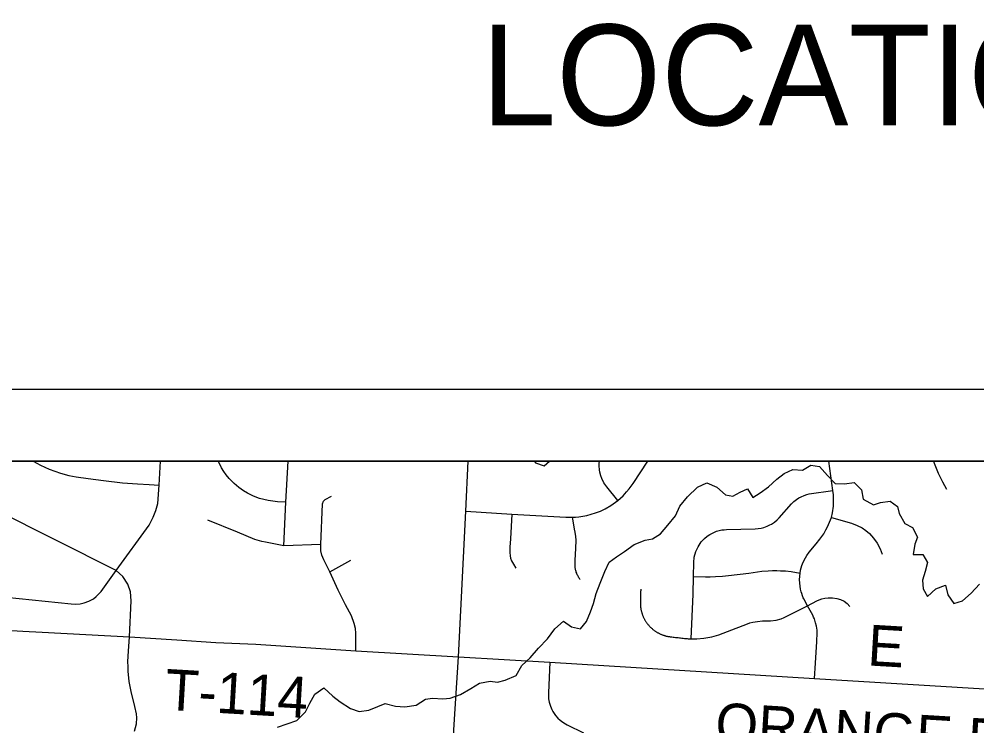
# Model space of a CAD drawing. Extents: x 0 to 34, y 0 to 22.
# Drawn here: x 4.859 to 6.189, y 9.816 to 10.798 of the extents above; entities that cross this region are included whole.
import ezdxf

# ---------------------------------------------------------------- set-up
doc = ezdxf.new("R2010")
doc.units = 0
for name, color, linetype in [('Default', 7, 'Continuous'), ('GM_X_Corporation', 7, 'Continuous'), ('GM_X_County_Road', 7, 'Continuous'), ('GM_X_Minor_Lake', 7, 'Continuous'), ('GM_X_Minor_River', 7, 'Continuous'), ('GM_X_Township_Road', 7, 'Continuous'), ('GM_X_Township_Road_Text', 7, 'Continuous'), ('SH_Data', 7, 'Continuous')]:
    doc.layers.add(name, color=color, linetype=linetype)

msp = doc.modelspace()

# ---------------------------------------------------------------- linework, layer by layer
at = {"layer": 'GM_X_Corporation'}
for points in [[(10.3182, 6.9963), (10.3182, 10.1841), (3.5182, 10.1841)], [(7.8118, 7.1421), (7.8248, 7.359), (7.8619, 7.9568), (7.8769, 8.1664), (7.8824, 8.2446), (7.9043, 8.6471), (7.9173, 8.8475), (7.9854, 9.7171), (7.9906, 9.8037), (8.012, 10.1113), (8.0168, 10.1841), (3.5182, 10.1841)]]:
    msp.add_lwpolyline(points, dxfattribs=at)
at = {"layer": 'GM_X_County_Road'}
for p, q in [((5.4792, 10.1147), (5.4826, 10.1841)), ((5.4689, 9.9123), (5.4792, 10.1147))]:
    msp.add_line(p, q, dxfattribs=at)
msp.add_lwpolyline([(5.3634, 8.9405), (5.3764, 8.9863), (5.3971, 9.0456), (5.406, 9.0826), (5.4131, 9.1059), (5.4187, 9.123), (5.4212, 9.1353), (5.4229, 9.1483), (5.4299, 9.2435), (5.4351, 9.34), (5.4391, 9.4072), (5.4451, 9.5207), (5.448, 9.5915), (5.4497, 9.6133), (5.4585, 9.7354), (5.4631, 9.818), (5.4689, 9.9123)], dxfattribs=at)
at = {"layer": 'GM_X_Minor_Lake'}
msp.add_lwpolyline([(5.5745, 10.1841), (5.5759, 10.1818), (5.588, 10.1776), (5.5952, 10.1841)], dxfattribs=at)
at = {"layer": 'GM_X_Minor_River'}
for points in [[(5.2175, 9.8146), (5.2312, 9.8192), (5.2444, 9.8237), (5.2565, 9.8359), (5.2625, 9.8477), (5.2697, 9.8602), (5.2822, 9.8689), (5.2947, 9.8576), (5.3045, 9.8496), (5.3189, 9.8405), (5.331, 9.836), (5.3443, 9.8379), (5.3571, 9.8433), (5.367, 9.8474), (5.3817, 9.8437), (5.3946, 9.8426), (5.4101, 9.8449), (5.423, 9.8532), (5.4328, 9.8548), (5.4472, 9.8536), (5.4574, 9.8548), (5.4718, 9.8598), (5.4862, 9.8681), (5.4983, 9.8757), (5.513, 9.8784), (5.5232, 9.8769), (5.5338, 9.8796), (5.5493, 9.8864), (5.5569, 9.9001), (5.5686, 9.9107), (5.5803, 9.9244), (5.5924, 9.9373), (5.6026, 9.951), (5.6147, 9.9616), (5.6261, 9.954), (5.6386, 9.951), (5.6469, 9.9613), (5.6522, 9.9745), (5.6563, 9.9863), (5.6601, 10.0003), (5.6657, 10.0144), (5.6722, 10.0307), (5.6782, 10.0436), (5.6884, 10.0512), (5.6997, 10.0584), (5.713, 10.0683), (5.7281, 10.074), (5.7383, 10.0763), (5.7497, 10.0831), (5.7599, 10.0949), (5.7701, 10.1082), (5.7765, 10.1215), (5.7871, 10.1344), (5.8007, 10.148), (5.8139, 10.1537), (5.8276, 10.1477), (5.8397, 10.1371), (5.8499, 10.1352), (5.8601, 10.1409), (5.8703, 10.1455), (5.8775, 10.1337), (5.8877, 10.1398), (5.8994, 10.1482), (5.9108, 10.1588), (5.921, 10.1668), (5.9331, 10.1725), (5.9467, 10.1714), (5.9581, 10.1786), (5.9702, 10.1767), (5.9815, 10.1639), (5.9922, 10.1529), (6.005, 10.1525), (6.0186, 10.1544), (6.0285, 10.1442), (6.0308, 10.1313), (6.0452, 10.1234), (6.055, 10.1264), (6.0682, 10.1284), (6.0785, 10.1208), (6.0811, 10.1113), (6.0887, 10.0973), (6.0993, 10.092), (6.1065, 10.0784), (6.1027, 10.0685), (6.1001, 10.0545), (6.1137, 10.0545), (6.1202, 10.0431)], [(6.1202, 10.0431), (6.1168, 10.0306), (6.1134, 10.0185), (6.1142, 10.0064), (6.1202, 9.9961), (6.1319, 10.0068), (6.1452, 10.0117), (6.1486, 9.9981), (6.1566, 9.9863), (6.169, 9.9898), (6.1808, 10.0008), (6.1925, 10.0133)]]:
    msp.add_lwpolyline(points, dxfattribs=at)
at = {"layer": 'GM_X_Township_Road'}
msp.add_line((5.2902, 10.0302), (5.3196, 10.0465), dxfattribs=at)
for points in [[(4.7823, 9.9908), (4.7997, 9.9963), (4.8045, 9.9973), (4.8086, 9.9978), (4.8119, 9.9979), (4.8169, 9.9976), (4.841, 9.9951), (4.9313, 9.9856), (4.9371, 9.9853), (4.9436, 9.9859), (4.9493, 9.9871), (4.9555, 9.9894), (4.962, 9.9929), (4.966, 9.9958), (4.973, 10.0028), (4.9938, 10.0319), (5.0395, 10.0951), (5.0449, 10.1063), (5.0488, 10.1155), (5.0515, 10.1251), (5.0532, 10.1508), (5.055, 10.1841)], [(4.878, 10.1841), (4.8782, 10.184), (4.8887, 10.1782), (4.9008, 10.1727), (4.9163, 10.1672), (4.9278, 10.1642), (4.938, 10.1622), (4.9546, 10.16), (4.9759, 10.1572), (5.0024, 10.1537), (5.0233, 10.1524), (5.0397, 10.1515), (5.0532, 10.1508)], [(5.2294, 10.127), (5.2178, 10.1276), (5.2045, 10.1292), (5.1926, 10.1322), (5.1842, 10.1354), (5.1761, 10.1393), (5.1705, 10.1427), (5.1638, 10.1475), (5.1575, 10.1528), (5.1507, 10.16), (5.1465, 10.1651), (5.1432, 10.1698), (5.1401, 10.1747), (5.1374, 10.1798), (5.1354, 10.1841)], [(5.2267, 10.0664), (5.2294, 10.127), (5.2326, 10.1841)], [(5.4792, 10.1147), (5.543, 10.1105), (5.6182, 10.1062), (5.6236, 10.106), (5.6271, 10.1061), (5.6314, 10.1064), (5.6363, 10.1067), (5.6471, 10.1085), (5.6593, 10.112), (5.666, 10.1147), (5.6726, 10.1178), (5.6805, 10.1224), (5.6903, 10.1294), (5.6975, 10.1359), (5.7025, 10.1412), (5.706, 10.1454), (5.7116, 10.153), (5.732, 10.1841)], [(5.6903, 10.1294), (5.6749, 10.1483), (5.6709, 10.154), (5.668, 10.1599), (5.6666, 10.1637), (5.6653, 10.1685), (5.6647, 10.1718), (5.6643, 10.1776), (5.6644, 10.1809), (5.6648, 10.1841)], [(5.9535, 9.9832), (5.9485, 9.9928), (5.9478, 9.9943), (5.9468, 9.9967), (5.9457, 10), (5.9449, 10.0025), (5.9441, 10.0062), (5.9433, 10.0104), (5.9428, 10.0147), (5.9426, 10.0195), (5.9432, 10.0283), (5.9441, 10.0325), (5.9459, 10.039), (5.9477, 10.0437), (5.9507, 10.0499), (5.9525, 10.053), (5.9557, 10.0576), (5.9656, 10.0691), (5.9709, 10.0757), (5.9736, 10.0793), (5.9761, 10.0832), (5.9792, 10.0885), (5.9812, 10.0926), (5.9868, 10.1057), (5.9883, 10.1122), (5.9889, 10.1153), (5.9893, 10.1184), (5.9896, 10.1215), (5.9898, 10.1246), (5.9899, 10.1308), (5.9898, 10.134), (5.9896, 10.1371), (5.9889, 10.1433), (5.9831, 10.1841)], [(6.1469, 10.1448), (6.1417, 10.1548), (6.1355, 10.1669), (6.1327, 10.1739), (6.1299, 10.1808), (6.129, 10.1841)], [(5.2902, 10.0302), (5.2819, 10.0468), (5.2792, 10.0536), (5.2777, 10.0592), (5.2777, 10.068), (5.2803, 10.1248), (5.2815, 10.1282), (5.2837, 10.1307), (5.2926, 10.1353)], [(5.7919, 9.9372), (5.7947, 9.999), (5.7952, 10.0237), (5.7956, 10.043), (5.7963, 10.0504), (5.7985, 10.0584), (5.8016, 10.0651), (5.8061, 10.0719), (5.8106, 10.0767), (5.8144, 10.0798), (5.8178, 10.0821), (5.8206, 10.0837), (5.8243, 10.0855), (5.8274, 10.0866), (5.8345, 10.0884), (5.8378, 10.0888), (5.841, 10.089), (5.8811, 10.09), (5.8852, 10.0903), (5.8893, 10.091), (5.8932, 10.0919), (5.8978, 10.0936), (5.9015, 10.0953), (5.9036, 10.0965), (5.9077, 10.0992), (5.9114, 10.1023), (5.9142, 10.1052), (5.9314, 10.1245), (5.9348, 10.1278), (5.9385, 10.1308), (5.9418, 10.133), (5.9447, 10.1346), (5.9491, 10.1365), (5.9529, 10.1376), (5.956, 10.1384), (5.9889, 10.1433)], [(5.0122, 9.9399), (5.0144, 9.99), (5.0135, 10.0024), (5.0099, 10.0133), (5.0031, 10.0236), (4.9938, 10.0319), (4.8258, 10.1162)], [(5.543, 10.1105), (5.5412, 10.0759), (5.5405, 10.0646), (5.5405, 10.057), (5.5407, 10.0526), (5.5413, 10.0493), (5.5427, 10.0456), (5.5454, 10.0407), (5.5487, 10.0353)], [(5.2777, 10.068), (5.2267, 10.0664), (5.2011, 10.0715), (5.1961, 10.0724), (5.1863, 10.0751), (5.1622, 10.0852), (5.1211, 10.1022)], [(5.6381, 10.0196), (5.6377, 10.0201), (5.637, 10.0211), (5.6363, 10.0221), (5.6357, 10.0231), (5.6351, 10.0241), (5.6345, 10.0252), (5.634, 10.0263), (5.6335, 10.0274), (5.6331, 10.0285), (5.6326, 10.0296), (5.6323, 10.0308), (5.6319, 10.0319), (5.6316, 10.0331), (5.6314, 10.0343), (5.6312, 10.0355), (5.631, 10.0367), (5.6309, 10.0379), (5.6308, 10.0391), (5.6308, 10.0403), (5.6308, 10.0415), (5.6308, 10.0427), (5.6309, 10.0436), (5.6309, 10.0446), (5.631, 10.0455), (5.631, 10.0465), (5.6311, 10.0474), (5.6311, 10.0483), (5.6312, 10.0493), (5.6312, 10.0502), (5.6313, 10.0512), (5.6313, 10.0521), (5.6313, 10.053), (5.6314, 10.054), (5.6314, 10.0549), (5.6315, 10.0559), (5.6315, 10.0568), (5.6316, 10.0577), (5.6316, 10.0587), (5.6317, 10.0596), (5.6317, 10.0605), (5.6318, 10.0615), (5.6318, 10.0624), (5.6319, 10.0634), (5.6319, 10.0643), (5.632, 10.0652), (5.632, 10.0662), (5.6321, 10.0671), (5.6321, 10.0681), (5.6322, 10.069), (5.6322, 10.0699), (5.6323, 10.0712), (5.6323, 10.0721), (5.6323, 10.0729), (5.6323, 10.0737), (5.6323, 10.0745), (5.6323, 10.0754), (5.6322, 10.0762), (5.6321, 10.077), (5.6321, 10.0778), (5.632, 10.0787), (5.6319, 10.0795), (5.6317, 10.0803), (5.6316, 10.0811), (5.6314, 10.082), (5.6313, 10.083), (5.6311, 10.0839), (5.6309, 10.0848), (5.6308, 10.0857), (5.6306, 10.0866), (5.6304, 10.0876), (5.6303, 10.0885), (5.6301, 10.0894), (5.63, 10.0904), (5.6298, 10.0913), (5.6296, 10.0922), (5.6295, 10.0931), (5.6293, 10.0941), (5.6291, 10.095), (5.629, 10.0959), (5.6288, 10.0968), (5.6286, 10.0978), (5.6285, 10.0987), (5.6283, 10.0996), (5.6281, 10.1005), (5.628, 10.1015), (5.6278, 10.1024), (5.6276, 10.1033), (5.6271, 10.1061)], [(5.9868, 10.1057), (6.0147, 10.0977), (6.0226, 10.0947), (6.0293, 10.0912), (6.0346, 10.0875), (6.0395, 10.0833), (6.0454, 10.077), (6.0504, 10.0699), (6.0543, 10.0622), (6.0574, 10.0547)], [(5.3266, 9.9206), (5.3266, 9.945), (5.3262, 9.9517), (5.3243, 9.9585), (5.3203, 9.9689), (5.3119, 9.9843), (5.3021, 10.005), (5.2902, 10.0302)], [(5.7952, 10.0237), (5.8118, 10.0232), (5.8184, 10.0231), (5.826, 10.0236), (5.8355, 10.0241), (5.844, 10.025), (5.872, 10.0286), (5.8903, 10.031), (5.8991, 10.0317), (5.9051, 10.032), (5.9111, 10.0319), (5.9162, 10.0318), (5.9195, 10.0317), (5.9231, 10.0314), (5.9307, 10.0305), (5.9432, 10.0283)], [(5.7221, 10.0063), (5.722, 10.0045), (5.7219, 10.0027), (5.7219, 10.0008), (5.7218, 9.999), (5.7218, 9.9972), (5.7217, 9.9954), (5.7217, 9.9935), (5.7216, 9.9917), (5.7216, 9.9899), (5.7215, 9.9891), (5.7215, 9.9883), (5.7215, 9.9875), (5.7215, 9.9866), (5.7215, 9.9858), (5.7215, 9.985), (5.7216, 9.9842), (5.7216, 9.9834), (5.7217, 9.9826), (5.7218, 9.9817), (5.7219, 9.9809), (5.722, 9.9801), (5.7221, 9.9793), (5.7222, 9.9785), (5.7224, 9.9777), (5.7226, 9.9769), (5.7227, 9.9761), (5.7229, 9.9753), (5.7231, 9.9745), (5.7234, 9.9737), (5.7236, 9.9729), (5.7239, 9.9722), (5.7241, 9.9714), (5.7244, 9.9706), (5.7247, 9.9699), (5.725, 9.9691), (5.7253, 9.9683), (5.7256, 9.9676), (5.726, 9.9669), (5.7263, 9.9661), (5.7267, 9.9654), (5.7271, 9.9647), (5.7275, 9.9639), (5.7279, 9.9632), (5.7283, 9.9625), (5.7287, 9.9618), (5.7292, 9.9611), (5.7296, 9.9605), (5.7301, 9.9598), (5.7306, 9.9591), (5.731, 9.9585), (5.7315, 9.9578), (5.732, 9.9572), (5.7326, 9.9566), (5.7331, 9.9559), (5.7336, 9.9553), (5.7342, 9.9547), (5.7348, 9.9541), (5.7353, 9.9535), (5.7359, 9.953), (5.7365, 9.9524), (5.7371, 9.9518), (5.7377, 9.9513), (5.7383, 9.9508), (5.739, 9.9503), (5.7396, 9.9497), (5.7403, 9.9492), (5.7409, 9.9488), (5.7416, 9.9483), (5.7423, 9.9478), (5.7429, 9.9474), (5.7436, 9.9469), (5.7443, 9.9465), (5.745, 9.9461), (5.7457, 9.9457), (5.7465, 9.9453), (5.7472, 9.9449), (5.7479, 9.9445), (5.7486, 9.9442), (5.7494, 9.9438), (5.7501, 9.9435), (5.7509, 9.9432), (5.7517, 9.9429), (5.7524, 9.9426), (5.7532, 9.9423), (5.754, 9.9421), (5.7547, 9.9418), (5.7555, 9.9416), (5.7563, 9.9413), (5.7571, 9.9411), (5.7579, 9.9409), (5.7587, 9.9408), (5.7595, 9.9406), (5.7603, 9.9404), (5.7611, 9.9403), (5.7619, 9.9402), (5.7627, 9.9401), (5.7635, 9.94), (5.7653, 9.9398), (5.767, 9.9396), (5.7687, 9.9394), (5.7705, 9.9392), (5.7722, 9.939), (5.7739, 9.9388), (5.7757, 9.9386), (5.7774, 9.9384), (5.7791, 9.9382), (5.7808, 9.938), (5.7826, 9.9378), (5.7844, 9.9376), (5.7863, 9.9375), (5.7881, 9.9373), (5.79, 9.9372), (5.7919, 9.9372), (5.7999, 9.9372), (5.8098, 9.938), (5.8207, 9.9399), (5.8303, 9.9426), (5.8545, 9.9518), (5.8678, 9.9573), (5.8735, 9.9592), (5.8779, 9.9603), (5.8842, 9.9614), (5.8909, 9.9621), (5.9024, 9.9624), (5.9099, 9.9632), (5.917, 9.965), (5.9213, 9.9666), (5.9296, 9.971), (5.9535, 9.9832)], [(5.9535, 9.9832), (5.9665, 9.9901), (5.9697, 9.9915), (5.9733, 9.9928), (5.9777, 9.9936), (5.9823, 9.9942), (5.9882, 9.9942), (5.9943, 9.9934), (5.9995, 9.9919), (6.0043, 9.9895), (6.0087, 9.9861), (6.0126, 9.9822)], [(5.9632, 9.8822), (5.9645, 9.9034), (5.9665, 9.9335), (5.967, 9.9454), (5.9668, 9.949), (5.966, 9.9547), (5.9649, 9.9596), (5.9631, 9.9649), (5.9621, 9.9672), (5.9608, 9.97), (5.9535, 9.9832)], [(4.5883, 9.9644), (4.6073, 9.9631), (4.6617, 9.9601), (4.7022, 9.9575), (4.7233, 9.9564), (4.7505, 9.9549), (4.7771, 9.9529), (4.7844, 9.9528), (4.8197, 9.9504), (4.8405, 9.9493), (4.8641, 9.9478), (4.891, 9.9462), (5.0122, 9.9399), (5.078, 9.9357), (5.1319, 9.9321), (5.1878, 9.9296), (5.3266, 9.9206), (5.4689, 9.9123)], [(5.0193, 9.8087), (5.0219, 9.819), (5.0223, 9.8276), (5.0217, 9.8332), (5.0195, 9.8433), (5.0143, 9.8641), (5.0118, 9.8781), (5.0103, 9.8924), (5.0101, 9.8985), (5.0099, 9.9057), (5.0107, 9.9202), (5.0122, 9.9399)], [(5.4689, 9.9123), (5.5957, 9.9046), (5.9632, 9.8822), (6.2604, 9.864), (6.4639, 9.8496), (6.6673, 9.838), (6.9796, 9.8194), (7.0349, 9.8181)], [(5.5957, 9.9046), (5.5939, 9.8623), (5.5939, 9.8573), (5.5942, 9.854), (5.5951, 9.8491), (5.5967, 9.8436), (5.5986, 9.8391), (5.6002, 9.8362), (5.601, 9.8348), (5.6039, 9.8307), (5.6071, 9.827), (5.6101, 9.8242), (5.614, 9.8212), (5.6174, 9.819), (5.62, 9.8177), (5.6427, 9.8065)]]:
    msp.add_lwpolyline(points, dxfattribs=at)
at = {"layer": 'SH_Data'}
for p, q in [((3.4182, 10.2841), (10.4182, 10.2841)), ((3.5182, 10.1841), (10.3182, 10.1841))]:
    msp.add_line(p, q, dxfattribs=at)

# ---------------------------------------------------------------- texts
at = {"layer": 'Default'}
msp.add_text('LOCATION 4 (FRA-71-29.62)', height=0.14, dxfattribs=at).set_placement((5.5007, 10.6505))
at = {"layer": 'GM_X_Township_Road_Text'}
for s, height, rotation, p in [('E', 0.0568, 356.6355, (6.036, 9.9003)), ('T-114', 0.05682, 356.6335, (5.0603, 9.8387)), ('ORANGE RD', 0.05682, 356.5707, (5.8244, 9.792))]:
    msp.add_text(s, height=height, rotation=rotation, dxfattribs=at).set_placement(p)

doc.saveas('drawing.dxf')
